Omron CX-Programmer project NuevoProyecto (CX-Programmer 9.50)

# PLC NewPLC1: CQM1 CPU21

## Program P12_2 (no task)
Local symbols
Etapa_0 10.00 BOOL
Etapa_1 10.01 BOOL
Etapa_2 10.02 BOOL
Etapa_3 10.03 BOOL
Etapa_4 10.04 BOOL
Etapa_5 10.05 BOOL
Etapa_6 10.06 BOOL
Etapa_7 10.07 BOOL
Etapa_8 10.08 BOOL
F1 0.01 BOOL
F2 0.02 BOOL
F3 0.03 BOOL
F4 0.04 BOOL
FSP 15.00 BOOL
P 0.00 BOOL
Pm 15.01 BOOL
Rd1 100.00 BOOL
Rd2 100.02 BOOL
Ri1 100.01 BOOL
Ri2 100.03 BOOL

### Section Sección1_Programa_principal
; Etapas 0 ... 8

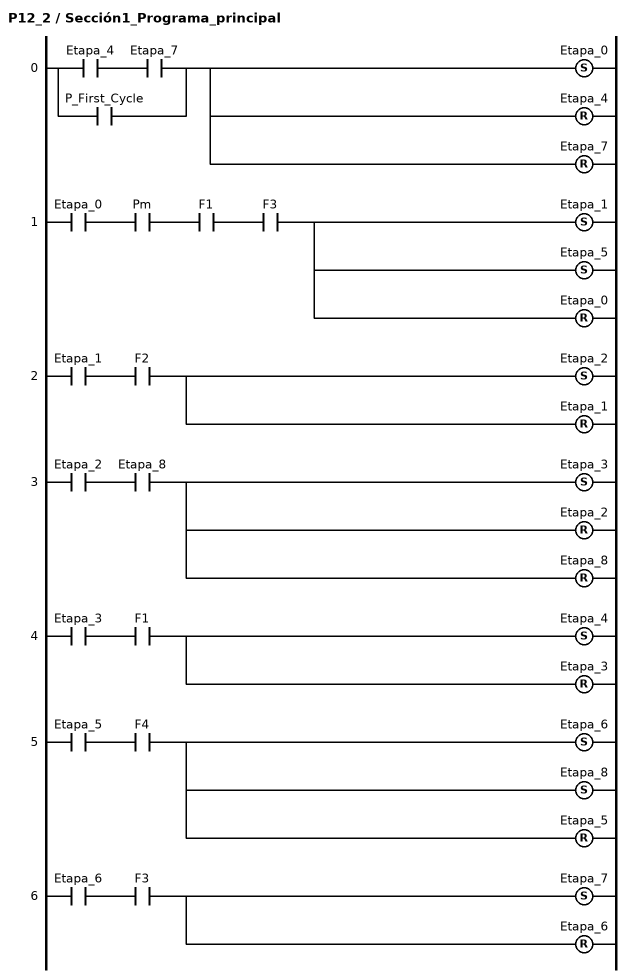
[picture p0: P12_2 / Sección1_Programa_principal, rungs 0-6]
; rung 0
LD Etapa_4
AND Etapa_7
OR P_First_Cycle
SET Etapa_0
RSET Etapa_4
RSET Etapa_7
; rung 1
LD Etapa_0
AND Pm
AND F1
AND F3
SET Etapa_1
SET Etapa_5
RSET Etapa_0
; rung 2
LD Etapa_1
AND F2
SET Etapa_2
RSET Etapa_1
; rung 3
LD Etapa_2
AND Etapa_8
SET Etapa_3
RSET Etapa_2
RSET Etapa_8
; rung 4
LD Etapa_3
AND F1
SET Etapa_4
RSET Etapa_3
; rung 5
LD Etapa_5
AND F4
SET Etapa_6
SET Etapa_8
RSET Etapa_5
; rung 6
LD Etapa_6
AND F3
SET Etapa_7
RSET Etapa_6

### Section Sección2_Paro_memorizado

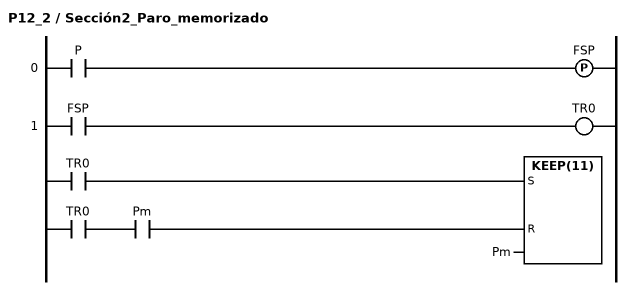
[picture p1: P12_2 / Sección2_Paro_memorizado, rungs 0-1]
; rung 0
LD P
DIFU(13) FSP
; rung 1
LD FSP
OUT TR0
LD TR0
AND Pm
KEEP(11) Pm

### Section Sección3_Salidas
; Salidas

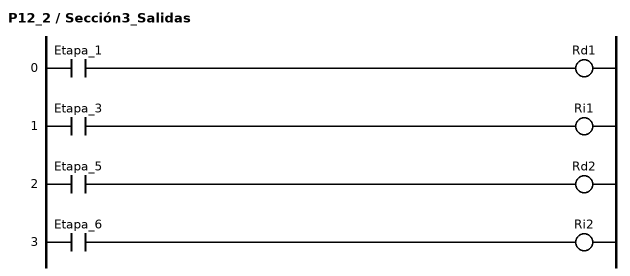
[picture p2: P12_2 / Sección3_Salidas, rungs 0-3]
; rung 0
LD Etapa_1
OUT Rd1
; rung 1
LD Etapa_3
OUT Ri1
; rung 2
LD Etapa_5
OUT Rd2
; rung 3
LD Etapa_6
OUT Ri2

### Section Sección4_END
; rung 0
END(01)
